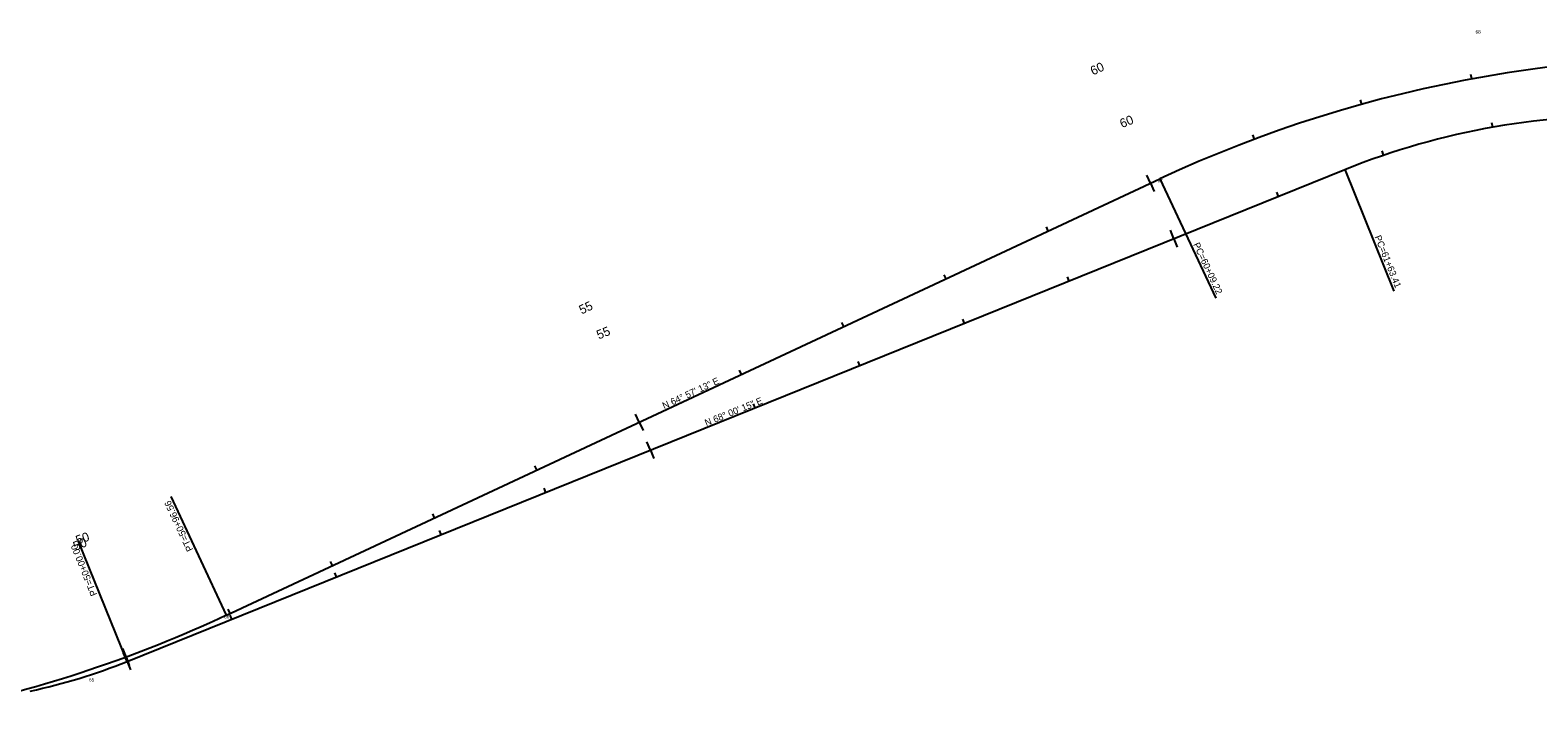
# Model space of a CAD drawing. Extents: x 1965771 to 1970246, y 1117124 to 1118239.
# Drawn here: x 1966685 to 1968020, y 1117406 to 1118007 of the extents above; entities that cross this region are included whole.
import ezdxf

# ---------------------------------------------------------------- set-up
doc = ezdxf.new("R2010")
doc.units = 0
for name, color, linetype in [('RD_HC_Cl', 7, 'Continuous'), ('RD_HC_Data', 7, 'Continuous'), ('RD_HC_Data_Tic', 7, 'Continuous'), ('RD_HC_Points', 7, 'Continuous'), ('RD_HC_TX_Sta50', 7, 'Continuous')]:
    doc.layers.add(name, color=color, linetype=linetype)

msp = doc.modelspace()

# ---------------------------------------------------------------- linework, layer by layer
at = {"layer": 'RD_HC_Cl'}
for p, q in [((1966770.7, 1117448.1), (1967849.5, 1117883.9)), ((1966858.9, 1117489.3), (1967685.7, 1117875.7))]:
    msp.add_line(p, q, dxfattribs=at)
for centre, radius, start, end in [((1968170.8, 1116837.5), 1145.9, 84.6661, 115.0463), ((1968094.4, 1117277.5), 653.9, 87.7266, 111.9958), ((1966373.7, 1118527.5), 1145.9, 281.9047, 295.0463), ((1966579.6, 1117921.3), 510.3, 281.9047, 291.9958)]:
    msp.add_arc(centre, radius, start, end, dxfattribs=at)
at = {"layer": 'RD_HC_Data'}
for p, q in [((1967685.7, 1117875.7), (1967735.1, 1117770.1)), ((1967849.5, 1117883.9), (1967892.9, 1117776.3)), ((1966858.9, 1117489.3), (1966809.8, 1117594.3)), ((1966770.7, 1117448.1), (1966727.4, 1117555.4))]:
    msp.add_line(p, q, dxfattribs=at)
at = {"layer": 'RD_HC_Data_Tic'}
for p, q in [((1967961.9, 1117964.2), (1967961.1, 1117968.1)), ((1967864.5, 1117941.7), (1967863.4, 1117945.6)), ((1967980.5, 1117921.5), (1967979.8, 1117925.4)), ((1967769.4, 1117910.8), (1967768, 1117914.6)), ((1967883.8, 1117896.6), (1967882.5, 1117900.4)), ((1967677.4, 1117871.8), (1967674, 1117879)), ((1967677.4, 1117871.8), (1967680.7, 1117864.5)), ((1967790.7, 1117860.1), (1967789.2, 1117863.8)), ((1967586.8, 1117829.4), (1967585.1, 1117833.1)), ((1967698, 1117822.7), (1967695, 1117830.1)), ((1967698, 1117822.7), (1967700.9, 1117815.2)), ((1967496.2, 1117787.1), (1967494.5, 1117790.7)), ((1967605.2, 1117785.2), (1967603.7, 1117788.9)), ((1967405.6, 1117744.8), (1967403.9, 1117748.4)), ((1967512.5, 1117747.7), (1967511, 1117751.5)), ((1967315, 1117702.4), (1967313.3, 1117706.1)), ((1967419.8, 1117710.3), (1967418.3, 1117714)), ((1967327.1, 1117672.8), (1967325.6, 1117676.5)), ((1967224.4, 1117660.1), (1967221, 1117667.3)), ((1967224.4, 1117660.1), (1967227.8, 1117652.8)), ((1967234.3, 1117635.4), (1967231.3, 1117642.8)), ((1967234.3, 1117635.4), (1967237.3, 1117628)), ((1967133.8, 1117617.8), (1967132.1, 1117621.4)), ((1967141.6, 1117597.9), (1967140.1, 1117601.6)), ((1967043.2, 1117575.4), (1967041.5, 1117579)), ((1967048.9, 1117560.5), (1967047.4, 1117564.2)), ((1966952.6, 1117533.1), (1966950.9, 1117536.7)), ((1966956.2, 1117523), (1966954.7, 1117526.7)), ((1966862, 1117490.8), (1966860.3, 1117494.4)), ((1966863.5, 1117485.6), (1966862, 1117489.3)), ((1966769.8, 1117452.2), (1966767, 1117459.7)), ((1966770.7, 1117448.1), (1966767.7, 1117455.5)), ((1966769.8, 1117452.2), (1966772.5, 1117444.6)), ((1966770.7, 1117448.1), (1966773.7, 1117440.7))]:
    msp.add_line(p, q, dxfattribs=at)

# ---------------------------------------------------------------- texts
at = {"layer": 'RD_HC_Data'}
for s, rotation, p in [('PC=61+63.41', 291.9958, (1967875.7, 1117824.3)), ('PC=60+09.22', 295.0463, (1967715, 1117817.6)), ('N 64%%d 57\' 13" E', 25.0463, (1967246.6, 1117671.6)), ('N 68%%d 00\' 15" E', 21.9958, (1967283.9, 1117656.5)), ('PT=50+96.56', 115.0463, (1966829.5, 1117547.3)), ('PT=50+00.00', 111.9958, (1966744.5, 1117507.6))]:
    msp.add_text(s, height=6, rotation=rotation, dxfattribs=at).set_placement(p)
at = {"layer": 'RD_HC_Points'}
for s, p in [('68', (1967965.3, 1118004.4)), ('67', (1967683.6, 1117872.7)), ('66', (1966856.7, 1117486.3)), ('65', (1966737, 1117430.4))]:
    msp.add_text(s, height=3, dxfattribs=at).set_placement(p)
at = {"layer": 'RD_HC_TX_Sta50'}
for s, rotation, p in [('60', 25.0463, (1967626.4, 1117967.2)), ('60', 21.9958, (1967652.1, 1117920.6)), ('55', 25.0463, (1967173.4, 1117755.5)), ('55', 21.9958, (1967188.6, 1117733.4)), ('50', 21.9958, (1966724.9, 1117546.1)), ('50', 20.2184, (1966727, 1117551.5))]:
    msp.add_text(s, height=8, rotation=rotation, dxfattribs=at).set_placement(p)

doc.saveas('drawing.dxf')
